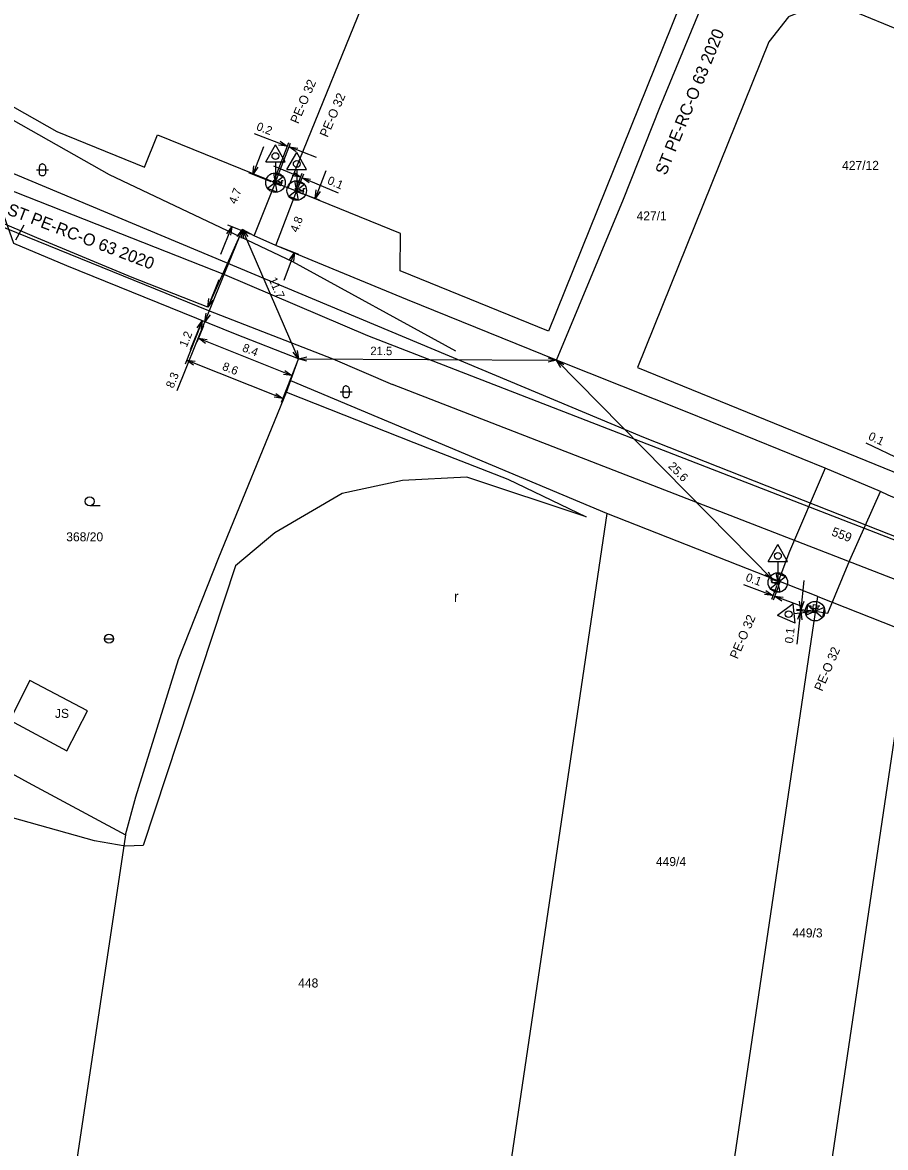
# Model space of a CAD drawing. Extents: x -836615 to -835459, y -1070675 to -1070205.
# Drawn here: x -836392.7 to -836320.9, y -1070473.1 to -1070379.5 of the extents above; entities that cross this region are included whole.
import ezdxf

# ---------------------------------------------------------------- set-up
doc = ezdxf.new("R2010")
doc.units = 0
for name, color, linetype in [('Budovy_kody', 7, 'Continuous'), ('Doprava_hranice', 7, 'Continuous'), ('OstPloch_hranice', 7, 'Continuous'), ('OstPloch_kody', 7, 'Continuous'), ('RuianPar_popis', 7, 'Continuous'), ('Stavby_hr_stav', 7, 'Continuous'), ('Stavby_kody', 7, 'Continuous'), ('Stavby_linie', 7, 'Continuous'), ('Vodstvo_body', 7, 'Continuous'), ('Vrstva 1', 7, 'Continuous'), ('Vrstva 21', 7, 'Continuous'), ('Vrstva 24', 7, 'Continuous'), ('Vrstva 31', 7, 'Continuous'), ('Vrstva 36', 7, 'Continuous'), ('Vrstva 37', 7, 'Continuous')]:
    doc.layers.add(name, color=color, linetype=linetype)

msp = doc.modelspace()

# ---------------------------------------------------------------- linework, layer by layer
at = {"layer": 'Budovy_kody'}
for p, q in [((-836344.06, -1070420.35), (-836370.359, -1070409.325)), ((-836318.87, -1070430.27), (-836338.19, -1070560.72)), ((-836384.11, -1070447.06), (-836408.18, -1070607.81))]:
    msp.add_line(p, q, dxfattribs=at)
for points in [[(-836373.08, -1070349.83), (-836376.1, -1070357.24), (-836380.96, -1070355.27), (-836383.64, -1070354.94), (-836385.94, -1070355.91), (-836387.56, -1070357.98), (-836398.1, -1070383.91), (-836389.8, -1070388.59), (-836382.53, -1070391.55), (-836381.43, -1070388.86), (-836370.56, -1070393.28), (-836355.76, -1070356.88), (-836342.51, -1070362.26), (-836345.53, -1070369.67), (-836340.66, -1070371.65), (-836338.69, -1070373.21), (-836338.03, -1070375.41), (-836338, -1070378.13), (-836348.92, -1070405.21), (-836361.26, -1070400.19), (-836361.24, -1070397.07), (-836370.56, -1070393.28)], [(-836316.11, -1070373), (-836319.13, -1070380.41), (-836323.99, -1070378.43), (-836326.67, -1070378.11), (-836328.97, -1070379.07), (-836330.59, -1070381.15), (-836341.51, -1070408.22), (-836318.77, -1070417.47), (-836302.87, -1070378.38), (-836290.49, -1070383.42), (-836293.5, -1070390.83), (-836288.73, -1070392.77), (-836286.67, -1070394.36), (-836285.68, -1070396.69), (-836285.97, -1070399.29), (-836295.88, -1070426.77), (-836318.77, -1070417.47)], [(-836393.4, -1070397.9), (-836395.84, -1070391.08), (-836341.03, -1070414.02), (-836301.19, -1070429.71), (-836266.57, -1070441.92)], [(-836326.51, -1070427.26), (-836344.06, -1070420.35), (-836360.72, -1070532.81)], [(-836346.11, -1070559.54), (-836326.51, -1070427.26), (-836318.87, -1070430.27)]]:
    msp.add_lwpolyline(points, dxfattribs=at)
at = {"layer": 'Doprava_hranice'}
for points in [[(-836363.94, -1070405.58), (-836375.83, -1070400.5), (-836396.2, -1070392.51), (-836412.22, -1070385.35), (-836415.3, -1070382.95)], [(-836417.67, -1070386.5), (-836404.61, -1070392.58), (-836394.98, -1070396.26), (-836377.21, -1070403.49), (-836366.86, -1070407.51), (-836361.89, -1070409.63)], [(-836015.21, -1070459.49), (-836021.84, -1070470.53), (-836029.29, -1070480.55), (-836039.31, -1070497.89), (-836043.1, -1070509.87), (-836044.22, -1070522.08), (-836111.13, -1070487.77), (-836123.74, -1070483.53), (-836128.61, -1070481.99), (-836211.76, -1070460.38), (-836245.95, -1070449.75), (-836279.43, -1070438.33), (-836363.94, -1070405.58)], [(-836046.6, -1070544.35), (-836045.64, -1070538.23), (-836044.38, -1070528.39), (-836045.14, -1070525.37), (-836047.92, -1070523.71), (-836112.97, -1070490.6), (-836124.66, -1070486.54), (-836132.47, -1070484.33), (-836212.77, -1070463.28), (-836247.95, -1070452.55), (-836280.73, -1070441.12), (-836361.89, -1070409.63)], [(-836370.7, -1070410.27), (-836360.12, -1070414.44), (-836352.3, -1070417.49), (-836345.8, -1070420.64)]]:
    msp.add_lwpolyline(points, dxfattribs=at)
at = {"layer": 'OstPloch_hranice'}
for points in [[(-836356.62, -1070406.87), (-836370.19, -1070399.44), (-836385.43, -1070392.2), (-836396.38, -1070386.03), (-836404.41, -1070381.11), (-836409.87, -1070376.61), (-836425.28, -1070363.93), (-836449.03, -1070345.44), (-836455, -1070340), (-836462.64, -1070329.11), (-836464.81, -1070325.47), (-836465.74, -1070321.03), (-836464.89, -1070314.87), (-836461.62, -1070306.74), (-836456.41, -1070297.54), (-836450.95, -1070288.2), (-836447.03, -1070272.79), (-836441.38, -1070260.76)], [(-836345.8, -1070420.64), (-836355.7, -1070417.34), (-836361.05, -1070417.62), (-836366.07, -1070418.7), (-836371.68, -1070421.97), (-836374.95, -1070424.71), (-836382.62, -1070447.97)], [(-836382.62, -1070447.97), (-836384.12, -1070448.01), (-836386.69, -1070447.56), (-836394.4, -1070445.42), (-836398.28, -1070444.88), (-836400.59, -1070445.48), (-836405.51, -1070448.52), (-836410.77, -1070452.46), (-836414.78, -1070467.48), (-836419.92, -1070491.57), (-836422.14, -1070507.07), (-836424.43, -1070527.13), (-836426.86, -1070555.21), (-836427.73, -1070571.17), (-836426.62, -1070578.67)]]:
    msp.add_lwpolyline(points, dxfattribs=at)
at = {"layer": 'OstPloch_kody'}
for p, q in [((-836391.51, -1070391.79), (-836390.51, -1070391.79)), ((-836391.26, -1070392.04), (-836391.26, -1070391.54)), ((-836390.76, -1070391.54), (-836390.76, -1070392.04)), ((-836366.26, -1070410.25), (-836365.26, -1070410.25)), ((-836366.01, -1070410.5), (-836366.01, -1070410)), ((-836365.51, -1070410), (-836365.51, -1070410.5)), ((-836386.205, -1070419.72), (-836387.08, -1070419.72))]:
    msp.add_line(p, q, dxfattribs=at)
for points in [[(-836391.01, -1070391.29), (-836391.055, -1070391.294), (-836391.102, -1070391.308), (-836391.147, -1070391.331), (-836391.187, -1070391.363), (-836391.219, -1070391.403), (-836391.242, -1070391.448), (-836391.256, -1070391.495), (-836391.26, -1070391.54)], [(-836391.01, -1070392.29), (-836391.055, -1070392.286), (-836391.102, -1070392.272), (-836391.147, -1070392.249), (-836391.187, -1070392.217), (-836391.219, -1070392.177), (-836391.242, -1070392.132), (-836391.256, -1070392.085), (-836391.26, -1070392.04)], [(-836391.01, -1070391.29), (-836390.965, -1070391.294), (-836390.918, -1070391.308), (-836390.873, -1070391.331), (-836390.833, -1070391.363), (-836390.801, -1070391.403), (-836390.778, -1070391.448), (-836390.764, -1070391.495), (-836390.76, -1070391.54)], [(-836390.76, -1070392.04), (-836390.764, -1070392.085), (-836390.778, -1070392.132), (-836390.801, -1070392.177), (-836390.833, -1070392.217), (-836390.873, -1070392.249), (-836390.918, -1070392.272), (-836390.965, -1070392.286), (-836391.01, -1070392.29)], [(-836365.76, -1070409.75), (-836365.805, -1070409.754), (-836365.852, -1070409.768), (-836365.897, -1070409.791), (-836365.937, -1070409.823), (-836365.969, -1070409.863), (-836365.992, -1070409.908), (-836366.006, -1070409.955), (-836366.01, -1070410)], [(-836365.76, -1070409.75), (-836365.715, -1070409.754), (-836365.668, -1070409.768), (-836365.623, -1070409.791), (-836365.583, -1070409.823), (-836365.551, -1070409.863), (-836365.528, -1070409.908), (-836365.514, -1070409.955), (-836365.51, -1070410)], [(-836365.76, -1070410.75), (-836365.805, -1070410.746), (-836365.852, -1070410.732), (-836365.897, -1070410.709), (-836365.937, -1070410.677), (-836365.969, -1070410.637), (-836365.992, -1070410.592), (-836366.006, -1070410.545), (-836366.01, -1070410.5)], [(-836365.51, -1070410.5), (-836365.514, -1070410.545), (-836365.528, -1070410.592), (-836365.551, -1070410.637), (-836365.583, -1070410.677), (-836365.623, -1070410.709), (-836365.668, -1070410.732), (-836365.715, -1070410.746), (-836365.76, -1070410.75)]]:
    msp.add_lwpolyline(points, dxfattribs=at)
msp.add_ellipse((-836387.08, -1070419.345), major_axis=(0.375, 0), ratio=0.999999, dxfattribs=at)
at = {"layer": 'Stavby_hr_stav'}
msp.add_lwpolyline([(-836387.27, -1070436.75), (-836392.07, -1070434.23), (-836393.73, -1070437.54), (-836388.97, -1070440.09), (-836387.27, -1070436.75)], dxfattribs=at)
at = {"layer": 'Stavby_linie'}
for points in [[(-836369.71, -1070407.51), (-836374.95, -1070405.45), (-836388.98, -1070399.76), (-836393.4, -1070397.9)], [(-836407.72, -1070434.26), (-836402.65, -1070436.98), (-836392.21, -1070442.72), (-836384.11, -1070447.06), (-836383.25, -1070443.91), (-836379.69, -1070432.5), (-836376.35, -1070424), (-836370.7, -1070410.27), (-836369.71, -1070407.51)]]:
    msp.add_lwpolyline(points, dxfattribs=at)
at = {"layer": 'Vodstvo_body'}
msp.add_line((-836385.855, -1070430.77), (-836385.105, -1070430.77), dxfattribs=at)
msp.add_circle((-836385.48, -1070430.77), 0.375, dxfattribs=at)
at = {"layer": 'Vrstva 1'}
for p, q in [((-836373.403, -1070388.77), (-836370.65, -1070389.826)), ((-836372.615, -1070389.885), (-836373.523, -1070392.161)), ((-836371.685, -1070392.523), (-836370.525, -1070389.499)), ((-836371.531, -1070392.582), (-836370.371, -1070389.558)), ((-836368.209, -1070390.762), (-836370.496, -1070389.885)), ((-836371.978, -1070392.777), (-836373.849, -1070392.031)), ((-836371.79, -1070391.451), (-836369.53, -1070392.397)), ((-836367.447, -1070391.876), (-836368.319, -1070394.165)), ((-836369.865, -1070393.197), (-836369.395, -1070392.074)), ((-836369.752, -1070393.244), (-836369.282, -1070392.121)), ((-836366.385, -1070393.713), (-836369.417, -1070392.444)), ((-836369.557, -1070393.693), (-836367.992, -1070394.29)), ((-836393.228, -1070397.595), (-836392.533, -1070396.361)), ((-836376.168, -1070398.789), (-836375.26, -1070396.514)), ((-836373.715, -1070397.13), (-836375.586, -1070396.384)), ((-836377.491, -1070404.42), (-836374.38, -1070396.75)), ((-836369.71, -1070407.51), (-836374.38, -1070396.75)), ((-836371.273, -1070398.195), (-836369.709, -1070398.791)), ((-836370.909, -1070400.956), (-836370.036, -1070398.666)), ((-836376.339, -1070400.93), (-836377.26, -1070403.2)), ((-836379.807, -1070410.131), (-836377.491, -1070404.42)), ((-836377.847, -1070404.653), (-836379.151, -1070407.934)), ((-836378.687, -1070406.719), (-836377.717, -1070404.328)), ((-836377.62, -1070404.745), (-836378.164, -1070406.116)), ((-836378.035, -1070405.791), (-836370.255, -1070408.881)), ((-836371.014, -1070410.791), (-836379.021, -1070407.609)), ((-836369.839, -1070407.835), (-836371.143, -1070411.116)), ((-836369.839, -1070407.835), (-836370.384, -1070409.207)), ((-836369.71, -1070407.51), (-836348.25, -1070407.6)), ((-836330.29, -1070425.83), (-836348.25, -1070407.6)), ((-836322.528, -1070414.485), (-836319.493, -1070415.922)), ((-836332.704, -1070426.255), (-836330.25, -1070427.177)), ((-836329.934, -1070426.338), (-836330.373, -1070427.505)), ((-836329.803, -1070426.388), (-836330.242, -1070427.554)), ((-836327.677, -1070425.923), (-836327.934, -1070428.36)), ((-836327.825, -1070428.089), (-836330.118, -1070427.227)), ((-836327.048, -1070428.563), (-836328.293, -1070428.432)), ((-836327.037, -1070428.455), (-836328.282, -1070428.323)), ((-836328.235, -1070431.217), (-836327.945, -1070428.469))]:
    msp.add_line(p, q, dxfattribs=at)
for points in [[(-836371.241, -1070389.412), (-836370.65, -1070389.826), (-836371.366, -1070389.739)], [(-836369.905, -1070390.299), (-836370.496, -1070389.885), (-836369.78, -1070389.972)], [(-836373.102, -1070391.575), (-836373.523, -1070392.161), (-836373.427, -1070391.446)], [(-836370.108, -1070391.965), (-836369.53, -1070392.397), (-836370.243, -1070392.288)], [(-836368.839, -1070392.876), (-836369.417, -1070392.444), (-836368.704, -1070392.553)], [(-836367.907, -1070393.573), (-836368.319, -1070394.165), (-836368.234, -1070393.448)], [(-836375.682, -1070397.099), (-836375.26, -1070396.514), (-836375.357, -1070397.229)], [(-836374.805, -1070397.333), (-836374.38, -1070396.75), (-836374.481, -1070397.464)], [(-836374.262, -1070397.462), (-836374.38, -1070396.75), (-836373.941, -1070397.322)], [(-836370.449, -1070399.258), (-836370.036, -1070398.666), (-836370.122, -1070399.383)], [(-836376.835, -1070402.617), (-836377.26, -1070403.2), (-836377.159, -1070402.486)], [(-836377.065, -1070403.837), (-836377.491, -1070404.42), (-836377.39, -1070403.705)], [(-836378.143, -1070404.911), (-836377.717, -1070404.328), (-836377.818, -1070405.042)], [(-836377.449, -1070406.212), (-836378.035, -1070405.791), (-836377.32, -1070405.887)], [(-836369.828, -1070406.798), (-836369.71, -1070407.51), (-836370.149, -1070406.938)], [(-836378.435, -1070408.03), (-836379.021, -1070407.609), (-836378.306, -1070407.704)], [(-836369.011, -1070407.688), (-836369.71, -1070407.51), (-836369.009, -1070407.338)], [(-836348.949, -1070407.422), (-836348.25, -1070407.6), (-836348.951, -1070407.772)], [(-836347.883, -1070408.221), (-836348.25, -1070407.6), (-836347.634, -1070407.976)], [(-836370.841, -1070408.46), (-836370.255, -1070408.881), (-836370.97, -1070408.786)], [(-836371.6, -1070410.37), (-836371.014, -1070410.791), (-836371.729, -1070410.695)], [(-836330.657, -1070425.209), (-836330.29, -1070425.83), (-836330.906, -1070425.454)], [(-836330.843, -1070426.767), (-836330.25, -1070427.177), (-836330.966, -1070427.095)], [(-836329.525, -1070427.637), (-836330.118, -1070427.227), (-836329.402, -1070427.309)], [(-836328.193, -1070429.146), (-836327.945, -1070428.469), (-836327.845, -1070429.183)], [(-836327.686, -1070427.682), (-836327.934, -1070428.36), (-836328.034, -1070427.645)]]:
    msp.add_lwpolyline(points, dxfattribs=at)
at = {"layer": 'Vrstva 21'}
for p, q in [((-836372.441, -1070391.107), (-836371.63, -1070389.702)), ((-836370.819, -1070391.107), (-836371.63, -1070389.702)), ((-836372.441, -1070391.107), (-836370.819, -1070391.107)), ((-836371.63, -1070391.107), (-836371.63, -1070392.85)), ((-836370.671, -1070391.757), (-836369.86, -1070390.352)), ((-836369.049, -1070391.757), (-836369.86, -1070390.352)), ((-836370.979, -1070392.366), (-836371.769, -1070392.05)), ((-836371.491, -1070393.65), (-836371.769, -1070392.05)), ((-836370.671, -1070391.757), (-836369.049, -1070391.757)), ((-836369.86, -1070391.757), (-836369.86, -1070393.5)), ((-836370.979, -1070392.366), (-836372.281, -1070393.334)), ((-836369.216, -1070393.005), (-836370.012, -1070392.703)), ((-836369.708, -1070394.297), (-836370.012, -1070392.703)), ((-836371.491, -1070393.65), (-836372.281, -1070393.334)), ((-836369.216, -1070393.005), (-836370.504, -1070393.995)), ((-836369.708, -1070394.297), (-836370.504, -1070393.995)), ((-836330.651, -1070424.347), (-836329.84, -1070422.942)), ((-836329.029, -1070424.347), (-836329.84, -1070422.942)), ((-836330.651, -1070424.347), (-836329.029, -1070424.347)), ((-836329.84, -1070424.347), (-836329.84, -1070426.09)), ((-836330.48, -1070426.589), (-836329.2, -1070425.591)), ((-836329.998, -1070425.294), (-836329.2, -1070425.591)), ((-836329.998, -1070425.294), (-836329.682, -1070426.886)), ((-836330.48, -1070426.589), (-836329.682, -1070426.886)), ((-836328.572, -1070427.867), (-836329.879, -1070428.829)), ((-836328.392, -1070429.479), (-836328.572, -1070427.867)), ((-836328.482, -1070428.673), (-836326.75, -1070428.48)), ((-836327.37, -1070427.956), (-836327.497, -1070428.798)), ((-836326.003, -1070428.162), (-836327.497, -1070428.798)), ((-836327.37, -1070427.956), (-836326.13, -1070429.004)), ((-836326.003, -1070428.162), (-836326.13, -1070429.004)), ((-836328.392, -1070429.479), (-836329.879, -1070428.829))]:
    msp.add_line(p, q, dxfattribs=at)
for centre, radius in [((-836371.63, -1070390.639), 0.282), ((-836369.86, -1070391.289), 0.282), ((-836371.63, -1070392.85), 0.812), ((-836369.86, -1070393.5), 0.812), ((-836329.84, -1070423.879), 0.282), ((-836329.84, -1070426.09), 0.812), ((-836328.948, -1070428.725), 0.282), ((-836326.75, -1070428.48), 0.812)]:
    msp.add_circle(centre, radius, dxfattribs=at)
at = {"layer": 'Vrstva 24'}
for p, q in [((-836373.39, -1070397.26), (-836371.63, -1070392.85)), ((-836371.6, -1070398.07), (-836369.86, -1070393.5))]:
    msp.add_line(p, q, dxfattribs=at)
for points in [[(-836348.25, -1070407.6), (-836342.69, -1070394.23), (-836339.65, -1070386.61), (-836332.49, -1070369.21), (-836332.29, -1070368.63), (-836332.18, -1070368.36)], [(-836348.25, -1070407.6), (-836360.66, -1070402.58), (-836371.6, -1070398.07), (-836373.39, -1070397.26), (-836374.38, -1070396.75), (-836377.26, -1070403.2), (-836383.55, -1070400.74), (-836391.47, -1070397.43), (-836398.19, -1070394.59), (-836403.86, -1070392.01)], [(-836290.9, -1070430.8), (-836293.5, -1070429.76), (-836296.3, -1070428.65), (-836301.68, -1070426.5), (-836305.56, -1070424.83), (-836318.9, -1070419.59), (-836320.66, -1070418.84), (-836321.3, -1070418.53), (-836325.9, -1070416.6), (-836337.38, -1070411.92), (-836348.25, -1070407.6)], [(-836325.9, -1070416.6), (-836328.88, -1070423.51), (-836329.84, -1070426.09)], [(-836326.75, -1070428.48), (-836325.69, -1070428.64), (-836323.85, -1070424.24), (-836321.3, -1070418.53)]]:
    msp.add_lwpolyline(points, dxfattribs=at)
at = {"layer": 'Vrstva 36'}
for p, q in [((-836371.832, -1070392.677), (-836371.712, -1070392.677)), ((-836371.712, -1070392.677), (-836371.712, -1070392.877)), ((-836371.712, -1070392.877), (-836371.112, -1070392.877)), ((-836371.112, -1070392.877), (-836371.112, -1070392.677)), ((-836371.112, -1070392.677), (-836370.978, -1070392.677)), ((-836370.02, -1070393.324), (-836369.899, -1070393.324)), ((-836369.899, -1070393.324), (-836369.899, -1070393.524)), ((-836369.899, -1070393.524), (-836369.299, -1070393.524)), ((-836369.299, -1070393.524), (-836369.299, -1070393.324)), ((-836369.299, -1070393.324), (-836369.165, -1070393.324)), ((-836330.461, -1070425.881), (-836330.34, -1070425.881)), ((-836330.34, -1070425.881), (-836330.34, -1070426.081)), ((-836330.34, -1070426.081), (-836329.74, -1070426.081)), ((-836329.74, -1070426.081), (-836329.74, -1070425.881)), ((-836329.74, -1070425.881), (-836329.606, -1070425.881)), ((-836327.218, -1070428.044), (-836327.098, -1070428.044)), ((-836327.098, -1070428.044), (-836327.098, -1070428.244)), ((-836327.098, -1070428.244), (-836326.498, -1070428.244)), ((-836326.498, -1070428.244), (-836326.498, -1070428.044)), ((-836326.498, -1070428.044), (-836326.364, -1070428.044))]:
    msp.add_line(p, q, dxfattribs=at)
at = {"layer": 'Vrstva 37'}
for p, q in [((-836371.81, -1070392.85), (-836371.18, -1070393.08)), ((-836370, -1070393.52), (-836369.39, -1070393.78)), ((-836330.29, -1070425.83), (-836329.68, -1070426.06)), ((-836326.64, -1070427.95), (-836326.7, -1070428.6))]:
    msp.add_line(p, q, dxfattribs=at)
for points in [[(-836371.81, -1070392.85), (-836371.72, -1070392.62), (-836371.09, -1070392.85), (-836371.18, -1070393.08)], [(-836370, -1070393.52), (-836369.9, -1070393.29), (-836369.29, -1070393.55), (-836369.39, -1070393.78)], [(-836329.68, -1070426.06), (-836329.77, -1070426.29), (-836330.38, -1070426.06), (-836330.29, -1070425.83)], [(-836326.7, -1070428.6), (-836326.95, -1070428.58), (-836326.89, -1070427.93), (-836326.64, -1070427.95)]]:
    msp.add_lwpolyline(points, dxfattribs=at)

# ---------------------------------------------------------------- texts
at = {"layer": 'OstPloch_kody'}
msp.add_text('r', height=0.9, dxfattribs=at).set_placement((-836356.79, -1070427.72))
at = {"layer": 'RuianPar_popis'}
for s, p in [('427/12', (-836324.502, -1070391.789)), ('427/1', (-836341.594, -1070395.984)), ('368/20', (-836389.03, -1070422.67)), ('449/4', (-836339.986, -1070449.669)), ('449/3', (-836328.631, -1070455.6)), ('448', (-836369.738, -1070459.763))]:
    msp.add_text(s, height=0.75, dxfattribs=at).set_placement(p)
msp.add_text('559', height=0.75, rotation=339.27018, dxfattribs=at).set_placement((-836325.439, -1070422.16))
at = {"layer": 'Stavby_kody'}
msp.add_text('JS', height=0.75, dxfattribs=at).set_placement((-836389.97, -1070437.35))
at = {"layer": 'Vrstva 1'}
for s, rotation, p in [('0.2', 339.01384, (-836373.277, -1070388.443)), ('0.1', 337.28596, (-836367.369, -1070392.922)), ('4.7', 68.24631, (-836374.908, -1070394.685)), ('4.8', 69.12886, (-836369.79, -1070397.04)), ('11.7', 293.46156, (-836372.202, -1070400.888)), ('1.2', 67.92452, (-836379.012, -1070406.588)), ('8.4', 338.3376, (-836374.446, -1070406.84)), ('21.5', 359.75971, (-836363.738, -1070407.185)), ('8.6', 338.32587, (-836376.112, -1070408.388)), ('8.3', 67.92452, (-836380.131, -1070410)), ('0.1', 334.66847, (-836322.379, -1070414.169)), ('25.6', 314.57255, (-836339.013, -1070416.477)), ('0.1', 339.40646, (-836332.581, -1070425.928)), ('0.1', 83.97806, (-836328.583, -1070431.18))]:
    msp.add_text(s, height=0.7, rotation=rotation, dxfattribs=at).set_placement(p)
at = {"layer": 'Vrstva 31'}
for s, height, rotation, p in [('ST PE-RC-O 63 2020', 1, 67.85707, (-836339.154, -1070392.295)), ('PE-O 32', 0.75, 66.78775, (-836369.741, -1070388.009)), ('PE-O 32', 0.75, 66.78775, (-836367.296, -1070389.138)), ('ST PE-RC-O 63 2020', 1, 339.06066, (-836394.023, -1070395.472)), ('PE-O 32', 0.75, 66.78775, (-836333.191, -1070432.511)), ('PE-O 32', 0.75, 66.78775, (-836326.162, -1070435.188))]:
    msp.add_text(s, height=height, rotation=rotation, dxfattribs=at).set_placement(p)

doc.saveas('drawing.dxf')
